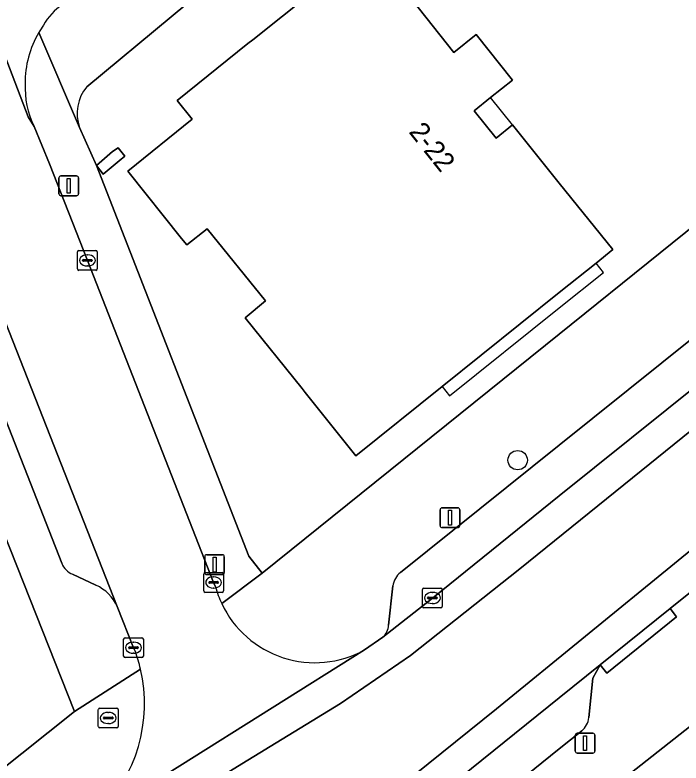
# Model space of a CAD drawing. Extents: x 161771 to 163125, y 382475 to 383179.
# Drawn here: x 161972.49 to 162006.15, y 382918.93 to 382956.71 of the extents above; entities that cross this region are included whole.
import ezdxf

# ---------------------------------------------------------------- set-up
doc = ezdxf.new("R2010")
doc.units = 0
for name, color, linetype in [('IMGEO_Boom', 7, 'Continuous'), ('IMGEO_Brandkraan', 7, 'Continuous'), ('IMGEO_Erf', 7, 'Continuous'), ('IMGEO_Kolk', 7, 'Continuous'), ('IMGEO_Lichtmast', 7, 'Continuous'), ('IMGEO_Pand', 7, 'Continuous'), ('IMGEO_Pand_nummerreeks', 7, 'Continuous'), ('IMGEO_Pand_overbouw', 7, 'Continuous'), ('IMGEO_Parkeervlak_open', 7, 'Continuous'), ('IMGEO_Rijbaan_lokaal_gesloten', 7, 'Continuous'), ('IMGEO_Rijbaan_lokaal_open', 7, 'Continuous'), ('IMGEO_Voetpad_open', 7, 'Continuous')]:
    doc.layers.add(name, color=color, linetype=linetype)

msp = doc.modelspace()

# ---------------------------------------------------------------- linework, layer by layer
at = {"layer": 'IMGEO_Boom'}
msp.add_circle((161997.897, 382934.227), 0.489, dxfattribs=at)
at = {"layer": 'IMGEO_Brandkraan'}
for p, q in [((161976.707, 382920.779), (161976.707, 382921.631)), ((161976.782, 382921.705), (161977.634, 382921.705)), ((161977.195, 382921.485), (161977.22, 382921.485)), ((161977.708, 382921.631), (161977.708, 382920.779)), ((161976.966, 382921.199), (161976.966, 382921.211)), ((161977.404, 382921.162), (161977.006, 382921.162)), ((161977.009, 382921.248), (161977.407, 382921.248)), ((161977.45, 382921.211), (161977.45, 382921.199)), ((161977.634, 382920.705), (161976.782, 382920.705)), ((161977.218, 382920.925), (161977.193, 382920.925))]:
    msp.add_line(p, q, dxfattribs=at)
for points in [[(161976.707, 382920.779), (161976.707, 382921.631)], [(161976.782, 382921.705), (161977.634, 382921.705)], [(161977.708, 382921.631), (161977.708, 382920.779)], [(161977.634, 382920.705), (161976.782, 382920.705)]]:
    msp.add_lwpolyline(points, dxfattribs=at)
for centre, radius, start, end in [((161976.784, 382921.629), 0.0765, 91.552, 178.448), ((161976.784, 382921.629), 0.0765, 91.552, 178.448), ((161977.632, 382921.629), 0.0765, 1.552, 88.448), ((161977.632, 382921.629), 0.0765, 1.552, 88.448), ((161977.006, 382921.208), 0.0403, 85.8775, 175.7526), ((161977.003, 382921.198), 0.0366, 178.938, 274.7102), ((161977.407, 382921.205), 0.043, 264.8664, 352.4533), ((161977.411, 382921.21), 0.0386, 1.7309, 96.639), ((161976.784, 382920.781), 0.0765, 181.552, 268.448), ((161976.784, 382920.781), 0.0765, 181.552, 268.448), ((161977.632, 382920.781), 0.0765, 271.552, 358.448), ((161977.632, 382920.781), 0.0765, 271.552, 358.448)]:
    msp.add_arc(centre, radius, start, end, dxfattribs=at)
for centre, major_axis, ratio, start_param, end_param in [((161977.194, 382921.205), (-0.387, 0.002), 0.722429, 4.712389, 7.853982), ((161977.219, 382921.205), (-0.39, 0.002), 0.717154, 1.570796, 4.712389)]:
    msp.add_ellipse(centre, major_axis=major_axis, ratio=ratio, start_param=start_param, end_param=end_param, dxfattribs=at)
at = {"layer": 'IMGEO_Erf'}
for points in [[(162046.723, 383011.3), (162033.035, 383000), (162000, 382972.728), (161984.645, 382960.165), (161976.127, 382953.087)], [(161975.763, 382951.026), (161976.607, 382949.106), (161984.305, 382929.382), (161984.99, 382928.524), (162000, 382940.599), (162020.411, 382957.018), (162045.2, 382976.96), (162050.138, 382980.891), (162052.963, 382983.141), (162071.005, 382997.699), (162069.245, 383000), (162068.408, 383001.095)], [(161948.535, 382900.058), (161975.504, 382921.534), (161964.156, 382950.157), (161955.527, 382971.976), (161932.987, 382962.833), (161922.636, 382958.708), (161930.525, 382940.74), (161944.655, 382908.555)], [(162035.035, 382915.547), (162030.61, 382921.288), (162025.213, 382928.29), (162028.097, 382930.608), (162024.72, 382935.013), (162021.921, 382932.844), (162021.355, 382932.4), (162000, 382915.572)]]:
    msp.add_lwpolyline(points, dxfattribs=at)
for points in [[(161996.531, 382952.542), (161995.702, 382951.87), (161996.806, 382950.485), (161997.63, 382951.162), (162000, 382948.218), (162002.702, 382944.861), (162001.861, 382944.182), (162000, 382942.69), (161994.077, 382937.942), (161989.717, 382934.454), (161987.153, 382937.65), (161987, 382937.85), (161984.134, 382941.413), (161985.16, 382942.282), (161982.207, 382945.905), (161981.184, 382945.103), (161980.914, 382945.427), (161978.197, 382948.83), (161981.447, 382951.455), (161980.692, 382952.396), (161984.27, 382955.265), (161984.506, 382955.461), (161990.422, 382960.193), (161994.677, 382954.82), (161995.795, 382955.727), (161997.641, 382953.427)], [(161976.607, 382949.106), (161977.419, 382949.811), (161977.706, 382950), (161978.047, 382949.58), (161977.766, 382949.349), (161976.946, 382948.675)]]:
    msp.add_lwpolyline(points, close=True, dxfattribs=at)
msp.add_arc((161977.724, 382951.742), 2.088, 139.9005, 200.0677, dxfattribs=at)
at = {"layer": 'IMGEO_Kolk'}
for p, q in [((161975.655, 382943.889), (161975.655, 382944.741)), ((161975.73, 382944.815), (161976.582, 382944.815)), ((161976.143, 382944.595), (161976.168, 382944.595)), ((161976.656, 382944.741), (161976.656, 382943.889)), ((161975.914, 382944.309), (161975.914, 382944.321)), ((161976.352, 382944.272), (161975.954, 382944.272)), ((161975.957, 382944.358), (161976.355, 382944.358)), ((161976.398, 382944.321), (161976.398, 382944.309)), ((161976.582, 382943.815), (161975.73, 382943.815)), ((161976.166, 382944.035), (161976.141, 382944.035)), ((161982.031, 382927.624), (161982.031, 382928.476)), ((161982.106, 382928.55), (161982.958, 382928.55)), ((161982.519, 382928.33), (161982.544, 382928.33)), ((161983.032, 382928.476), (161983.032, 382927.624)), ((161982.29, 382928.044), (161982.29, 382928.056)), ((161982.728, 382928.007), (161982.33, 382928.007)), ((161982.333, 382928.093), (161982.731, 382928.093)), ((161982.774, 382928.056), (161982.774, 382928.044)), ((161982.958, 382927.55), (161982.106, 382927.55)), ((161982.542, 382927.77), (161982.517, 382927.77)), ((161993.088, 382926.84), (161993.088, 382927.692)), ((161993.163, 382927.766), (161994.015, 382927.766)), ((161993.576, 382927.546), (161993.601, 382927.546)), ((161994.089, 382927.692), (161994.089, 382926.84)), ((161993.347, 382927.26), (161993.347, 382927.272)), ((161993.785, 382927.223), (161993.387, 382927.223)), ((161993.39, 382927.309), (161993.788, 382927.309)), ((161993.831, 382927.272), (161993.831, 382927.26)), ((161994.015, 382926.766), (161993.163, 382926.766)), ((161993.599, 382926.986), (161993.574, 382926.986)), ((161978.058, 382925.255), (161978.91, 382925.255)), ((161977.983, 382924.329), (161977.983, 382925.181)), ((161978.471, 382925.035), (161978.496, 382925.035)), ((161978.984, 382925.181), (161978.984, 382924.329)), ((161978.242, 382924.749), (161978.242, 382924.761)), ((161978.68, 382924.712), (161978.282, 382924.712)), ((161978.285, 382924.798), (161978.683, 382924.798)), ((161978.494, 382924.475), (161978.469, 382924.475)), ((161978.726, 382924.761), (161978.726, 382924.749)), ((161978.91, 382924.255), (161978.058, 382924.255))]:
    msp.add_line(p, q, dxfattribs=at)
for points in [[(161975.655, 382943.889), (161975.655, 382944.741)], [(161975.73, 382944.815), (161976.582, 382944.815)], [(161976.656, 382944.741), (161976.656, 382943.889)], [(161976.582, 382943.815), (161975.73, 382943.815)], [(161982.031, 382927.624), (161982.031, 382928.476)], [(161982.106, 382928.55), (161982.958, 382928.55)], [(161983.032, 382928.476), (161983.032, 382927.624)], [(161982.958, 382927.55), (161982.106, 382927.55)], [(161993.088, 382926.84), (161993.088, 382927.692)], [(161993.163, 382927.766), (161994.015, 382927.766)], [(161994.089, 382927.692), (161994.089, 382926.84)], [(161994.015, 382926.766), (161993.163, 382926.766)], [(161978.058, 382925.255), (161978.91, 382925.255)], [(161977.983, 382924.329), (161977.983, 382925.181)], [(161978.984, 382925.181), (161978.984, 382924.329)], [(161978.91, 382924.255), (161978.058, 382924.255)]]:
    msp.add_lwpolyline(points, dxfattribs=at)
for centre, radius, start, end in [((161975.732, 382944.739), 0.0765, 91.552, 178.448), ((161975.732, 382944.739), 0.0765, 91.552, 178.448), ((161976.58, 382944.739), 0.0765, 1.552, 88.448), ((161976.58, 382944.739), 0.0765, 1.552, 88.448), ((161975.954, 382944.318), 0.0403, 85.8775, 175.7526), ((161975.951, 382944.308), 0.0366, 178.938, 274.7102), ((161976.355, 382944.315), 0.043, 264.8664, 352.4533), ((161976.359, 382944.32), 0.0386, 1.7309, 96.639), ((161975.732, 382943.891), 0.0765, 181.552, 268.448), ((161975.732, 382943.891), 0.0765, 181.552, 268.448), ((161976.58, 382943.891), 0.0765, 271.552, 358.448), ((161976.58, 382943.891), 0.0765, 271.552, 358.448), ((161982.108, 382928.474), 0.0765, 91.552, 178.448), ((161982.108, 382928.474), 0.0765, 91.552, 178.448), ((161982.956, 382928.474), 0.0765, 1.552, 88.448), ((161982.956, 382928.474), 0.0765, 1.552, 88.448), ((161982.33, 382928.053), 0.0403, 85.8775, 175.7526), ((161982.327, 382928.043), 0.0366, 178.938, 274.7102), ((161982.731, 382928.05), 0.043, 264.8664, 352.4533), ((161982.735, 382928.055), 0.0386, 1.7309, 96.639), ((161982.108, 382927.626), 0.0765, 181.552, 268.448), ((161982.108, 382927.626), 0.0765, 181.552, 268.448), ((161982.956, 382927.626), 0.0765, 271.552, 358.448), ((161982.956, 382927.626), 0.0765, 271.552, 358.448), ((161993.165, 382927.69), 0.0765, 91.552, 178.448), ((161993.165, 382927.69), 0.0765, 91.552, 178.448), ((161994.013, 382927.69), 0.0765, 1.552, 88.448), ((161994.013, 382927.69), 0.0765, 1.552, 88.448), ((161993.387, 382927.269), 0.0403, 85.8775, 175.7526), ((161993.384, 382927.259), 0.0366, 178.938, 274.7102), ((161993.788, 382927.266), 0.043, 264.8664, 352.4533), ((161993.792, 382927.271), 0.0386, 1.7309, 96.639), ((161993.165, 382926.842), 0.0765, 181.552, 268.448), ((161993.165, 382926.842), 0.0765, 181.552, 268.448), ((161994.013, 382926.842), 0.0765, 271.552, 358.448), ((161994.013, 382926.842), 0.0765, 271.552, 358.448), ((161978.06, 382925.179), 0.0765, 91.552, 178.448), ((161978.06, 382925.179), 0.0765, 91.552, 178.448), ((161978.908, 382925.179), 0.0765, 1.552, 88.448), ((161978.908, 382925.179), 0.0765, 1.552, 88.448), ((161978.282, 382924.758), 0.0403, 85.8775, 175.7526), ((161978.279, 382924.748), 0.0366, 178.938, 274.7102), ((161978.683, 382924.755), 0.043, 264.8664, 352.4533), ((161978.687, 382924.76), 0.0386, 1.7309, 96.639), ((161978.06, 382924.331), 0.0765, 181.552, 268.448), ((161978.06, 382924.331), 0.0765, 181.552, 268.448), ((161978.908, 382924.331), 0.0765, 271.552, 358.448), ((161978.908, 382924.331), 0.0765, 271.552, 358.448)]:
    msp.add_arc(centre, radius, start, end, dxfattribs=at)
for centre, major_axis, ratio, start_param, end_param in [((161976.142, 382944.315), (-0.387, 0.002), 0.722429, 4.712389, 7.853982), ((161976.167, 382944.315), (-0.39, 0.002), 0.717154, 1.570796, 4.712389), ((161982.518, 382928.05), (-0.387, 0.002), 0.722429, 4.712389, 7.853982), ((161982.543, 382928.05), (-0.39, 0.002), 0.717154, 1.570796, 4.712389), ((161993.575, 382927.266), (-0.387, 0.002), 0.722429, 4.712389, 7.853982), ((161993.6, 382927.266), (-0.39, 0.002), 0.717154, 1.570796, 4.712389), ((161978.47, 382924.755), (-0.387, 0.002), 0.722429, 4.712389, 7.853982), ((161978.495, 382924.755), (-0.39, 0.002), 0.717154, 1.570796, 4.712389)]:
    msp.add_ellipse(centre, major_axis=major_axis, ratio=ratio, start_param=start_param, end_param=end_param, dxfattribs=at)
at = {"layer": 'IMGEO_Lichtmast'}
for p, q in [((161974.716, 382947.683), (161974.716, 382948.483)), ((161974.716, 382948.483), (161974.716, 382947.683)), ((161974.816, 382948.583), (161975.606, 382948.583)), ((161975.606, 382948.583), (161974.816, 382948.583)), ((161975.706, 382948.483), (161975.706, 382947.683)), ((161975.706, 382947.683), (161975.706, 382948.483)), ((161975.606, 382947.583), (161974.816, 382947.583)), ((161974.816, 382947.583), (161975.606, 382947.583)), ((161993.979, 382930.922), (161993.979, 382931.722)), ((161993.979, 382931.722), (161993.979, 382930.922)), ((161994.079, 382931.822), (161994.869, 382931.822)), ((161994.869, 382931.822), (161994.079, 382931.822)), ((161994.969, 382931.722), (161994.969, 382930.922)), ((161994.969, 382930.922), (161994.969, 382931.722)), ((161994.869, 382930.822), (161994.079, 382930.822)), ((161994.079, 382930.822), (161994.869, 382930.822)), ((161982.184, 382929.45), (161982.974, 382929.45)), ((161982.974, 382929.45), (161982.184, 382929.45)), ((161982.084, 382928.55), (161982.084, 382929.35)), ((161982.084, 382929.35), (161982.084, 382928.55)), ((161983.074, 382929.35), (161983.074, 382928.55)), ((161983.074, 382928.55), (161983.074, 382929.35)), ((161982.974, 382928.45), (161982.184, 382928.45)), ((161982.184, 382928.45), (161982.974, 382928.45)), ((162000.809, 382919.531), (162000.809, 382920.331)), ((162000.809, 382920.331), (162000.809, 382919.531)), ((162000.909, 382920.431), (162001.699, 382920.431)), ((162001.699, 382920.431), (162000.909, 382920.431)), ((162001.799, 382920.331), (162001.799, 382919.531)), ((162001.799, 382919.531), (162001.799, 382920.331)), ((162001.699, 382919.431), (162000.909, 382919.431)), ((162000.909, 382919.431), (162001.699, 382919.431))]:
    msp.add_line(p, q, dxfattribs=at)
for points in [[(161975.136, 382948.458), (161975.286, 382948.458), (161975.286, 382947.708), (161975.136, 382947.708), (161975.136, 382948.458)], [(161994.399, 382931.697), (161994.549, 382931.697), (161994.549, 382930.947), (161994.399, 382930.947), (161994.399, 382931.697)], [(161982.504, 382929.325), (161982.654, 382929.325), (161982.654, 382928.575), (161982.504, 382928.575), (161982.504, 382929.325)], [(162001.229, 382920.306), (162001.379, 382920.306), (162001.379, 382919.556), (162001.229, 382919.556), (162001.229, 382920.306)]]:
    msp.add_lwpolyline(points, dxfattribs=at)
for centre, start, end in [((161974.816, 382948.483), 90, 180), ((161974.816, 382948.483), 90, 180), ((161975.606, 382948.483), 0, 90), ((161975.606, 382948.483), 360, 90), ((161974.816, 382947.683), 180, 270), ((161974.816, 382947.683), 180, 270), ((161975.606, 382947.683), 270, 0), ((161975.606, 382947.683), 270, 0), ((161994.079, 382931.722), 90, 180), ((161994.079, 382931.722), 90, 180), ((161994.869, 382931.722), 0, 90), ((161994.869, 382931.722), 360, 90), ((161994.079, 382930.922), 180, 270), ((161994.079, 382930.922), 180, 270), ((161994.869, 382930.922), 270, 0), ((161994.869, 382930.922), 270, 0), ((161982.184, 382929.35), 90, 180), ((161982.184, 382929.35), 90, 180), ((161982.974, 382929.35), 0, 90), ((161982.974, 382929.35), 360, 90), ((161982.184, 382928.55), 180, 270), ((161982.184, 382928.55), 180, 270), ((161982.974, 382928.55), 270, 0), ((161982.974, 382928.55), 270, 0), ((162000.909, 382920.331), 90, 180), ((162000.909, 382920.331), 90, 180), ((162001.699, 382920.331), 0, 90), ((162001.699, 382920.331), 360, 90), ((162000.909, 382919.531), 180, 270), ((162000.909, 382919.531), 180, 270), ((162001.699, 382919.531), 270, 0), ((162001.699, 382919.531), 270, 0)]:
    msp.add_arc(centre, 0.1, start, end, dxfattribs=at)
at = {"layer": 'IMGEO_Pand'}
for points in [[(161996.531, 382952.542), (161997.641, 382953.427), (161995.795, 382955.727), (161994.677, 382954.82), (161990.422, 382960.193), (161984.506, 382955.461), (161984.27, 382955.265), (161980.692, 382952.396), (161981.447, 382951.455), (161978.197, 382948.83), (161980.914, 382945.427), (161981.184, 382945.103), (161982.207, 382945.905), (161985.16, 382942.282), (161984.134, 382941.413), (161987, 382937.85), (161987.153, 382937.65), (161989.717, 382934.454), (161994.077, 382937.942), (162000, 382942.69), (162001.861, 382944.182), (162002.702, 382944.861), (162000, 382948.218), (161997.63, 382951.162), (161996.806, 382950.485), (161995.702, 382951.87)], [(161976.607, 382949.106), (161976.946, 382948.675), (161977.766, 382949.349), (161978.047, 382949.58), (161977.706, 382950), (161977.419, 382949.811)]]:
    msp.add_lwpolyline(points, close=True, dxfattribs=at)
at = {"layer": 'IMGEO_Pand_overbouw'}
for points in [[(161996.531, 382952.542), (161995.702, 382951.87), (161996.806, 382950.485), (161997.63, 382951.162)], [(162001.861, 382944.182), (162000, 382942.69), (161994.077, 382937.942), (161994.453, 382937.478), (162000, 382941.918), (162002.236, 382943.708)]]:
    msp.add_lwpolyline(points, close=True, dxfattribs=at)
at = {"layer": 'IMGEO_Parkeervlak_open'}
for points in [[(161977.654, 382926.832), (161971.239, 382943.112), (161962.344, 382965.829), (161955.317, 382983.812), (161949.478, 382998.607)], [(161948.885, 382995.16), (161960.75, 382965.015), (161974.867, 382929.022)], [(161991.08, 382925.282), (161993.59, 382927.265), (162000, 382932.42), (162007.212, 382938.219), (162022.376, 382950.374)], [(162019.044, 382950.252), (162000, 382934.987), (161991.97, 382928.55)], [(161975.405, 382928.462), (161976.584, 382927.907)], [(161991.595, 382927.873), (161991.377, 382925.897)], [(162001.499, 382921.225), (162001.694, 382923.221), (162002.067, 382923.882), (162000, 382922.219), (161990.01, 382914.184), (161987.316, 382912.037)], [(161987.978, 382912.169), (161989.836, 382912.009), (161990.697, 382912.147), (162000, 382919.642), (162001.131, 382920.553)]]:
    msp.add_lwpolyline(points, dxfattribs=at)
for centre, radius, start, end in [((161975.74, 382929.323), 0.924, 198.9912, 248.7131), ((161992.597, 382927.76), 1.008, 128.4473, 173.5873), ((161975.782, 382926.039), 2.033, 22.9666, 66.7663), ((161990.505, 382925.939), 0.873, 311.2004, 357.2453), ((162000.386, 382921.398), 1.127, 311.4185, 351.1696)]:
    msp.add_arc(centre, radius, start, end, dxfattribs=at)
at = {"layer": 'IMGEO_Rijbaan_lokaal_gesloten'}
for points in [[(161971.98, 382910.499), (161979.179, 382915.935), (161979.294, 382916.006), (161983.958, 382918.885), (161988.947, 382921.944), (161992.488, 382924.359), (161998, 382928.746), (162025.43, 382950.879), (162047.566, 382968.998), (162116.302, 383026.353), (162142.919, 383048.007), (162155.349, 383059.528), (162157.47, 383063.478), (162155.928, 383063.813), (162155.408, 383063.926)], [(162064.893, 382976.459), (162098.092, 383005.831), (162135.752, 383036.849), (162160.98, 383057.918), (162164.197, 383062.015), (162157.47, 383063.478), (162155.349, 383059.528), (162142.919, 383048.007), (162116.302, 383026.353), (162047.566, 382968.998), (162025.43, 382950.879), (161998, 382928.746), (161992.488, 382924.359), (161988.947, 382921.944), (161983.958, 382918.885), (161979.294, 382916.006)], [(162164.558, 383059.775), (162164.975, 383060.328), (162165.507, 383060.724), (162166.652, 383061.481), (162166.023, 383061.618), (162164.197, 383062.015), (162160.98, 383057.918), (162135.752, 383036.849), (162098.092, 383005.831), (162064.893, 382976.459), (162028.312, 382947.355), (161996.833, 382921.662), (161989.309, 382915.625), (161975.267, 382904.355), (161969.513, 382899.968), (161964.685, 382896.828), (161958.891, 382892.441), (161953.057, 382887.933), (161929.84, 382869.578), (161924.324, 382865.246), (161911.803, 382855.192)], [(162145.413, 383052.14), (162142.917, 383050.128), (162125.562, 383035.892), (162100.16, 383015.252), (162093.593, 383009.676), (162084.717, 383002.102), (162084.439, 383001.844), (162082.922, 383000.604), (162082.268, 383000), (162072.619, 382991.712), (162072.447, 382991.552), (162052.085, 382974.632), (162039.559, 382964.378), (162029.724, 382956.315), (162026.381, 382953.619), (162024.462, 382952.063), (162022.504, 382950.476), (162022.376, 382950.374), (162007.212, 382938.219), (162000, 382932.42), (161993.59, 382927.265), (161991.08, 382925.282), (161990.16, 382924.643), (161976.155, 382915.855)], [(161911.803, 382855.192), (161924.324, 382865.246), (161929.84, 382869.578), (161953.057, 382887.933), (161958.891, 382892.441), (161964.685, 382896.828), (161969.513, 382899.968), (161975.267, 382904.355), (161989.309, 382915.625), (161996.833, 382921.662), (162028.312, 382947.355), (162064.893, 382976.459)], [(161972.821, 382900.329), (161973.787, 382901.113), (161982.468, 382908.125), (161987.067, 382911.839), (161987.316, 382912.037), (161990.01, 382914.184), (162000, 382922.219), (162002.067, 382923.882), (162005.598, 382926.729), (162012.02, 382931.882), (162014.915, 382934.221), (162018.466, 382937.053), (162023.002, 382940.692), (162026.254, 382943.301), (162029.478, 382945.93), (162030.983, 382947.158), (162034.035, 382949.646), (162034.624, 382950.119), (162044.627, 382958.275)]]:
    msp.add_lwpolyline(points, dxfattribs=at)
at = {"layer": 'IMGEO_Rijbaan_lokaal_open'}
for points in [[(161947.533, 383017.528), (161942.983, 383015.58), (161943.332, 383014.713), (161944.007, 383012.809), (161946.34, 383006.744), (161947.885, 383002.626), (161948.26, 383001.581), (161948.711, 383000.633), (161948.95, 383000), (161949.428, 382998.734), (161949.478, 382998.607), (161955.317, 382983.812), (161962.344, 382965.829), (161971.239, 382943.112), (161977.654, 382926.832), (161978.485, 382924.755), (161978.58, 382924.549)], [(161982.63, 382927.831), (161982.531, 382928.049), (161976.155, 382944.315), (161974.236, 382949.194), (161973.461, 382951.082), (161973.157, 382951.56), (161968.39, 382964.05), (161968.383, 382964.151), (161966.823, 382968.082)], [(161968.383, 382964.151), (161968.39, 382964.05), (161973.157, 382951.56), (161973.461, 382951.082)], [(161976.721, 382916.411), (161976.155, 382915.855), (161990.16, 382924.643)]]:
    msp.add_lwpolyline(points, dxfattribs=at)
for centre, radius, start, end in [((161976.403, 382954.87), 2.798, 122.315, 151.8346), ((161978.07, 382953.25), 5.073, 144.5658, 149.5073), ((161977.98, 382953.299), 4.972, 149.4715, 180.4907), ((161977.513, 382953.058), 4.508, 177.4878, 206.0024), ((161987.563, 382929.173), 5.112, 195.2174, 205.3761), ((161987.651, 382929.202), 5.204, 205.2478, 298.833), ((161971.367, 382921.939), 7.671, 13.1054, 19.8944), ((161971.316, 382921.927), 7.723, 314.4141, 13.1024)]:
    msp.add_arc(centre, radius, start, end, dxfattribs=at)
at = {"layer": 'IMGEO_Voetpad_open'}
for points in [[(162073.055, 382998.553), (162071.887, 383000), (162069.976, 383002.366), (162068.408, 383001.095), (162069.245, 383000), (162071.005, 382997.699), (162052.963, 382983.141), (162050.138, 382980.891), (162045.2, 382976.96), (162020.411, 382957.018), (162000, 382940.599), (161984.99, 382928.524), (161982.944, 382926.982)], [(161945.407, 382998.406), (161948.531, 382991.013), (161948.047, 382990.809), (161948.269, 382990.251), (161948.435, 382989.833), (161948.823, 382988.855), (161953.791, 382976.347), (161955.527, 382971.976), (161964.156, 382950.157), (161975.504, 382921.534), (161978.838, 382923.678)], [(161974.867, 382929.022), (161960.75, 382965.015), (161948.885, 382995.16)], [(161976.127, 382953.087), (161984.645, 382960.165)], [(161976.607, 382949.106), (161975.763, 382951.026), (161973.698, 382955.824)], [(161973.698, 382955.824), (161975.763, 382951.026)], [(161973.461, 382951.082), (161974.236, 382949.194), (161976.155, 382944.315), (161982.531, 382928.049), (161982.63, 382927.831)], [(162000, 382934.987), (162019.044, 382950.252)], [(161982.944, 382926.982), (161984.99, 382928.524), (161984.305, 382929.382), (161976.607, 382949.106)], [(162021.355, 382932.4), (162021.921, 382932.844), (162018.783, 382936.642), (162015.248, 382933.807), (162014.915, 382934.221), (162012.02, 382931.882), (162005.598, 382926.729), (162005.927, 382926.309), (162002.403, 382923.476), (162002.067, 382923.882), (162001.694, 382923.221), (162001.499, 382921.225)], [(161991.97, 382928.55), (162000, 382934.987)], [(161987.316, 382912.037), (161987.067, 382911.839), (161990.238, 382907.88), (162000, 382915.572), (162021.355, 382932.4)], [(161976.584, 382927.907), (161975.405, 382928.462)], [(161991.377, 382925.897), (161991.595, 382927.873)], [(161978.58, 382924.549), (161978.485, 382924.755), (161977.654, 382926.832)], [(161990.16, 382924.643), (161991.08, 382925.282)], [(161978.838, 382923.678), (161975.504, 382921.534), (161948.535, 382900.058), (161951.054, 382894.925), (161909.943, 382862.484), (161902.967, 382857.371), (161901.316, 382856.161), (161903.978, 382854.245)], [(162001.131, 382920.553), (162000, 382919.642), (161990.697, 382912.147), (161989.836, 382912.009), (161987.978, 382912.169)]]:
    msp.add_lwpolyline(points, dxfattribs=at)
msp.add_lwpolyline([(162002.067, 382923.882), (162002.403, 382923.476), (162005.927, 382926.309), (162005.598, 382926.729)], close=True, dxfattribs=at)
for centre, radius, start, end in [((161976.403, 382954.87), 2.798, 122.315, 151.8346), ((161978.07, 382953.25), 5.073, 144.5658, 149.5073), ((161977.98, 382953.299), 4.972, 149.4715, 180.4907), ((161977.513, 382953.058), 4.508, 177.4878, 206.0024), ((161977.724, 382951.742), 2.088, 139.9005, 200.0677), ((161975.74, 382929.323), 0.924, 198.9912, 248.7131), ((161992.597, 382927.76), 1.008, 128.4473, 173.5873), ((161975.782, 382926.039), 2.033, 22.9666, 66.7663), ((161987.563, 382929.173), 5.112, 195.2174, 205.3761), ((161987.651, 382929.202), 5.204, 205.2478, 298.833), ((161990.505, 382925.939), 0.873, 311.2004, 357.2453), ((161971.367, 382921.939), 7.671, 13.1054, 19.8944), ((161971.316, 382921.927), 7.723, 314.4141, 13.1024), ((162000.386, 382921.398), 1.127, 311.4185, 351.1696)]:
    msp.add_arc(centre, radius, start, end, dxfattribs=at)

# ---------------------------------------------------------------- texts
at = {"layer": 'IMGEO_Pand_nummerreeks'}
msp.add_text('2-22', height=1, rotation=308.5588, dxfattribs=at).set_placement((161992.362, 382950.797))

doc.saveas('drawing.dxf')
